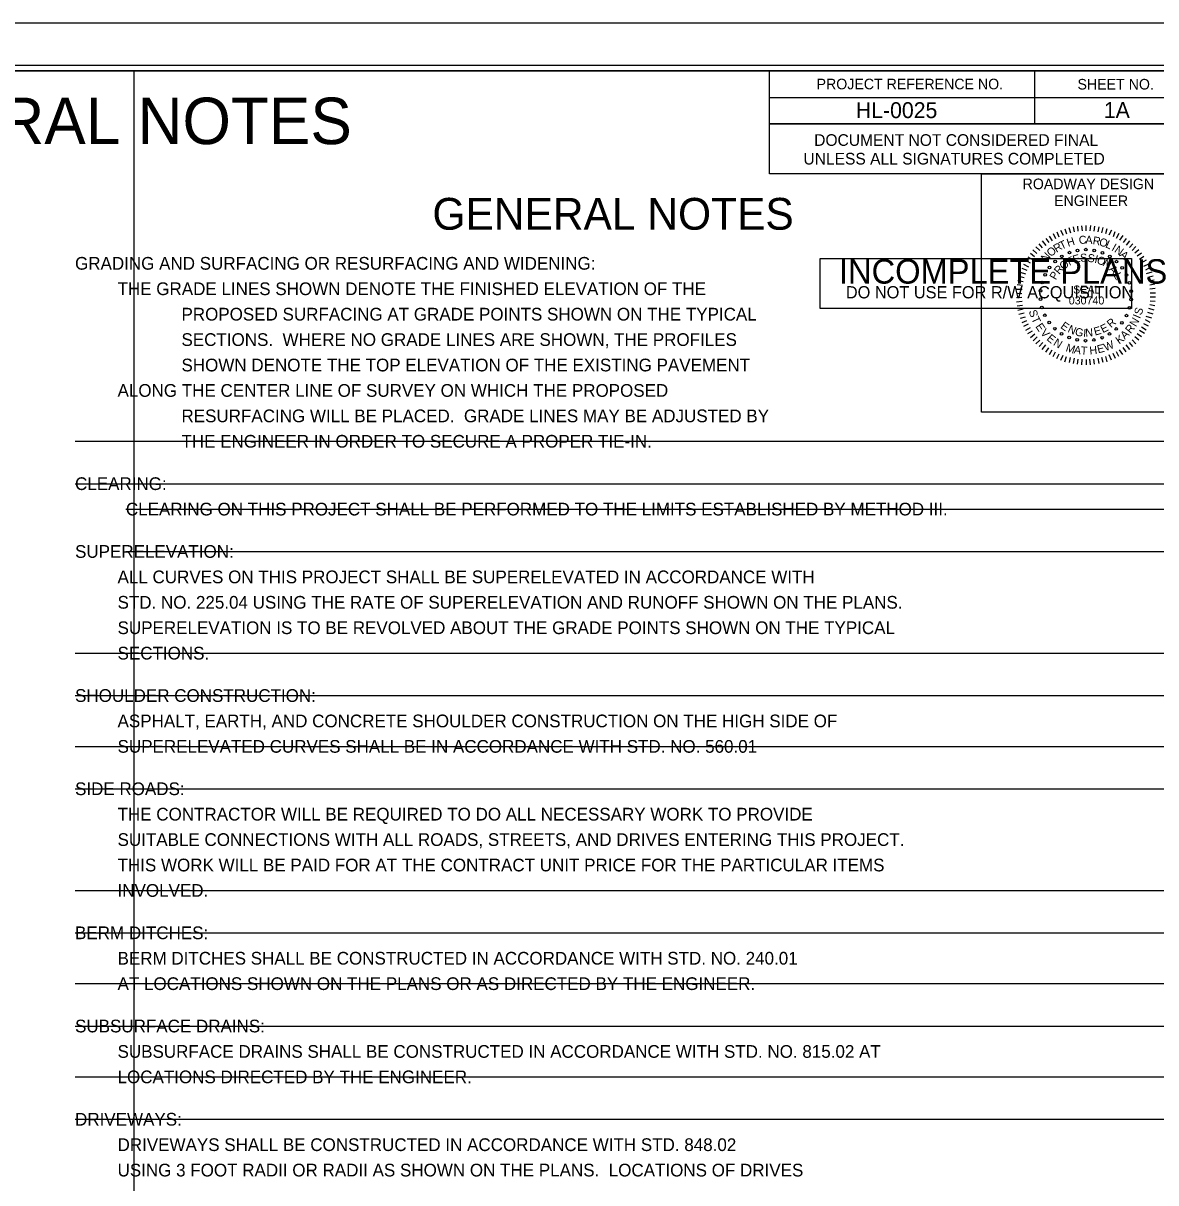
# Model space of a CAD drawing. Extents: x -1492 to 2447, y -56 to 1953.
# Drawn here: x 948 to 1482, y 525 to 1072 of the extents above; entities that cross this region are included whole.
import ezdxf

# ---------------------------------------------------------------- set-up
doc = ezdxf.new("R2010")
doc.units = 0
for name, color, linetype in [('Old_Level_9', 7, 'Continuous'), ('Scratch_Level_3', 7, 'Continuous'), ('Sheet Cutting Line CELL', 7, 'Continuous'), ('Sheet Data Field CELL', 7, 'Continuous'), ('Sheet Data Text CELL', 7, 'Continuous'), ('Sheet Plan CELL', 7, 'Continuous'), ('Sheet Plot Border Inside CELL', 7, 'Continuous'), ('Sheet Plot Border Outside CELL', 7, 'Continuous'), ('Sheet Sticker Exception Certification CELL', 7, 'Continuous'), ('Sheet Sticker Incomplete CELL', 7, 'Continuous'), ('Sheet Summary CELL', 7, 'Continuous')]:
    doc.layers.add(name, color=color, linetype=linetype)

msp = doc.modelspace()

# ---------------------------------------------------------------- linework, layer by layer
at = {"layer": 'Old_Level_9'}
for p, q in [((1437.28, 974.82), (1438.48, 972.42)), ((1439.38, 975.42), (1440.08, 973.02)), ((1441.28, 976.02), (1441.98, 973.52)), ((1443.18, 976.42), (1443.68, 974.02)), ((1445.28, 976.72), (1445.48, 974.32)), ((1447.18, 976.82), (1447.48, 974.42)), ((1449.28, 977.02), (1449.28, 974.42)), ((1451.38, 977.02), (1451.08, 974.42)), ((1453.28, 976.72), (1453.08, 974.32)), ((1455.38, 976.42), (1454.88, 974.02)), ((1457.28, 976.02), (1456.58, 973.62)), ((1459.18, 975.42), (1458.48, 973.02)), ((1461.28, 974.82), (1460.08, 972.42)), ((1428.68, 969.72), (1430.28, 967.62)), ((1430.28, 970.92), (1431.78, 968.92)), ((1431.88, 972.02), (1433.38, 969.82)), ((1433.78, 973.22), (1434.98, 970.82)), ((1435.58, 974.02), (1436.48, 971.72)), ((1462.98, 974.02), (1462.08, 971.72)), ((1464.78, 973.22), (1463.58, 970.82)), ((1466.68, 972.22), (1465.18, 970.02)), ((1468.28, 970.92), (1466.78, 968.92)), ((1469.88, 969.72), (1468.28, 967.72)), ((1423.18, 963.92), (1425.08, 962.32)), ((1424.28, 965.52), (1426.18, 963.82)), ((1425.68, 966.92), (1427.48, 965.22)), ((1427.08, 968.42), (1428.68, 966.52)), ((1471.48, 968.42), (1469.88, 966.62)), ((1472.88, 967.12), (1471.08, 965.22)), ((1474.28, 965.52), (1472.38, 963.92)), ((1475.58, 963.92), (1473.48, 962.52)), ((1419.78, 958.72), (1422.18, 957.52)), ((1420.78, 960.62), (1422.98, 959.32)), ((1421.88, 962.22), (1424.08, 960.92)), ((1476.68, 962.32), (1474.58, 960.92)), ((1477.78, 960.62), (1475.58, 959.32)), ((1478.78, 958.82), (1476.38, 957.72)), ((1417.58, 953.12), (1420.08, 952.42)), ((1418.18, 955.02), (1420.78, 954.22)), ((1418.98, 956.92), (1421.38, 955.92)), ((1479.58, 957.12), (1477.38, 955.92)), ((1480.38, 955.02), (1477.78, 954.22)), ((1480.98, 953.12), (1478.48, 952.42)), ((1416.58, 947.02), (1419.18, 946.92)), ((1416.78, 949.12), (1419.28, 948.82)), ((1417.08, 951.02), (1419.58, 950.52)), ((1481.48, 951.22), (1478.98, 950.72)), ((1481.78, 949.32), (1479.38, 948.82)), ((1481.98, 947.22), (1479.38, 946.92)), ((1416.48, 945.12), (1418.98, 944.92)), ((1416.48, 943.02), (1418.98, 943.22)), ((1482.08, 945.12), (1479.58, 945.12)), ((1482.08, 943.22), (1479.58, 943.22)), ((1416.58, 941.02), (1419.18, 941.32)), ((1416.78, 939.02), (1419.28, 939.42)), ((1417.08, 937.02), (1419.58, 937.62)), ((1481.48, 937.12), (1478.98, 937.82)), ((1481.78, 939.02), (1479.38, 939.52)), ((1481.98, 941.12), (1479.58, 941.32)), ((1417.68, 935.12), (1420.08, 935.72)), ((1418.38, 933.22), (1420.78, 933.92)), ((1419.18, 931.22), (1421.38, 932.22)), ((1419.98, 929.52), (1422.18, 930.62)), ((1478.78, 929.52), (1476.58, 930.62)), ((1479.58, 931.22), (1477.38, 932.42)), ((1480.38, 933.22), (1477.78, 934.12)), ((1480.98, 935.22), (1478.48, 935.92)), ((1420.88, 927.62), (1423.18, 928.82)), ((1421.88, 926.02), (1424.08, 927.32)), ((1423.18, 924.22), (1425.18, 925.82)), ((1475.58, 924.42), (1473.48, 925.82)), ((1476.88, 926.02), (1474.58, 927.42)), ((1477.78, 927.62), (1475.58, 929.02)), ((1424.38, 922.62), (1426.28, 924.42)), ((1425.68, 921.22), (1427.58, 922.92)), ((1427.28, 919.82), (1428.88, 921.72)), ((1428.68, 918.52), (1430.28, 920.62)), ((1469.98, 918.52), (1468.28, 920.62)), ((1471.48, 919.92), (1469.88, 921.72)), ((1472.88, 921.22), (1471.08, 923.12)), ((1474.28, 922.82), (1472.38, 924.42)), ((1430.28, 917.22), (1431.78, 919.32)), ((1432.08, 916.12), (1433.38, 918.32)), ((1433.78, 915.12), (1434.98, 917.42)), ((1435.58, 914.22), (1436.68, 916.42)), ((1437.48, 913.42), (1438.48, 915.82)), ((1439.38, 912.72), (1440.18, 915.12)), ((1441.48, 912.32), (1441.98, 914.72)), ((1443.38, 911.82), (1443.88, 914.32)), ((1455.48, 911.82), (1454.98, 914.32)), ((1457.38, 912.32), (1456.78, 914.72)), ((1459.28, 912.72), (1458.68, 915.12)), ((1461.28, 913.42), (1460.28, 915.92)), ((1463.18, 914.22), (1462.08, 916.62)), ((1464.88, 915.12), (1463.78, 917.42)), ((1466.68, 916.12), (1465.18, 918.32)), ((1468.28, 917.42), (1466.78, 919.42)), ((1445.28, 911.52), (1445.58, 913.92)), ((1447.38, 911.32), (1447.48, 913.92)), ((1449.48, 911.22), (1449.48, 913.72)), ((1451.38, 911.32), (1451.18, 913.92)), ((1453.38, 911.52), (1453.08, 913.92))]:
    msp.add_line(p, q, dxfattribs=at)
for centre in [(1441.51, 964.19), (1445.33, 965.26), (1449.28, 965.61), (1453.23, 965.23), (1457.04, 964.13), (1434.78, 960.06), (1437.95, 962.43), (1460.58, 962.35), (1463.74, 959.94), (1430, 953.77), (1432.1, 957.14), (1466.4, 957), (1468.47, 953.62), (1428.55, 950.08), (1469.89, 949.92), (1427.79, 942.22), (1427.81, 946.19), (1470.59, 942.05), (1470.6, 946.02), (1428.51, 938.32), (1469.84, 938.16), (1429.92, 934.62), (1432, 931.24), (1466.29, 931.1), (1468.39, 934.47), (1434.66, 928.3), (1437.81, 925.9), (1460.44, 925.81), (1463.61, 928.18), (1441.36, 924.11), (1445.17, 923.01), (1449.11, 922.63), (1453.06, 922.98), (1456.88, 924.05)]:
    msp.add_circle(centre, 0.63, dxfattribs=at)
at = {"layer": 'Scratch_Level_3'}
for p, q in [((500, 1050), (1000, 1050)), ((1000, 1050), (1000, -2.5)), ((1000, 1050), (1500, 1050)), ((972.18, 875.15), (1722.72, 875.15)), ((972.18, 855.15), (1722.72, 855.15)), ((996.18, 843.15), (1692.22, 843.15)), ((996.18, 823.15), (1692.22, 823.15)), ((972.18, 775.15), (1722.72, 775.15)), ((972.18, 755.15), (1722.72, 755.15)), ((972.18, 731.15), (1722.72, 731.15)), ((972.18, 711.15), (1722.72, 711.15)), ((972.18, 663.15), (1722.72, 663.15)), ((972.18, 643.15), (1722.72, 643.15)), ((972.18, 619.15), (1722.72, 619.15)), ((972.18, 599.15), (1722.72, 599.15)), ((972.18, 575.15), (1722.72, 575.15)), ((972.18, 555.15), (1722.72, 555.15))]:
    msp.add_line(p, q, dxfattribs=at)
at = {"layer": 'Sheet Cutting Line CELL'}
msp.add_line((1517, 1072.5), (-166.5, 1072.5), dxfattribs=at)
at = {"layer": 'Sheet Plan CELL'}
for p, q in [((1425, 1049.95), (1425, 1024.95)), ((1299.95, 1037.45), (1500, 1037.45)), ((1299.95, 1024.95), (1500, 1024.95)), ((1299.95, 1024.95), (1500, 1024.95))]:
    msp.add_line(p, q, dxfattribs=at)
for points in [[(1500, 1050), (0, 1050), (0, 0), (1500, 0)], [(1299.95, 1050), (1500, 1050), (1500, 1024.95), (1299.95, 1024.95)], [(1399.99, 1001.45), (1499.99, 1001.45), (1499.99, 888.95), (1399.99, 888.95)]]:
    msp.add_lwpolyline(points, close=True, dxfattribs=at)
at = {"layer": 'Sheet Plot Border Inside CELL'}
msp.add_lwpolyline([(-153.5, -2.5), (1512.5, -2.5), (1512.5, 1052.5), (-153.5, 1052.5)], close=True, dxfattribs=at)
at = {"layer": 'Sheet Plot Border Outside CELL'}
msp.add_lwpolyline([(-166.5, -22.5), (1517, -22.5), (1517, 1072.5), (-166.5, 1072.5)], close=True, dxfattribs=at)
at = {"layer": 'Sheet Sticker Exception Certification CELL'}
for p, q in [((1299.95, 1001.45), (1299.95, 1024.95)), ((1299.95, 1024.95), (1499.99, 1024.95)), ((1499.99, 1001.45), (1299.95, 1001.45))]:
    msp.add_line(p, q, dxfattribs=at)
at = {"layer": 'Sheet Sticker Incomplete CELL'}
msp.add_lwpolyline([(1323.77, 937.87), (1323.77, 961.37), (1470.77, 961.37), (1470.77, 937.87)], close=True, dxfattribs=at)

# ---------------------------------------------------------------- texts
at = {"layer": 'Old_Level_9'}
for s, height, rotation, p in [('T', 3.78, 25.4358, (1437.78, 965.52)), ('H', 3.78, 17.7433, (1440.88, 966.92)), ('C', 3.78, 4.9399, (1446.08, 968.22)), ('A', 3.78, 357.9749, (1448.98, 968.42)), ('R', 3.78, 350.0216, (1452.28, 968.22)), ('O', 3.78, 343.0868, (1455.18, 967.72)), ('L', 3.78, 335.7459, (1458.18, 966.82)), ('N', 3.78, 48.0667, (1430.48, 959.52)), ('O', 3.78, 39.9442, (1432.68, 962.02)), ('R', 3.78, 32.1754, (1435.38, 964.12)), ('E', 3.76, 16.5889, (1443.68, 959.02)), ('S', 3.76, 4.468, (1446.68, 959.82)), ('S', 3.76, 353.0415, (1449.88, 959.92)), ('I', 3.78, 330.806, (1461.08, 965.42)), ('N', 3.78, 324.9038, (1462.38, 964.72)), ('A', 3.78, 317.0051, (1464.88, 962.82)), ('R', 3.76, 49.7478, (1436.68, 953.62)), ('O', 3.76, 38.2518, (1438.58, 955.82)), ('F', 3.76, 26.4, (1441.48, 957.92)), ('I', 3.76, 345.4821, (1453.08, 959.52)), ('O', 3.76, 337.8749, (1454.08, 959.32)), ('N', 3.76, 327.393, (1456.78, 958.22)), ('P', 3.76, 60.1236, (1435.08, 951.02)), ('A', 3.76, 313.9438, (1459.78, 956.12)), ('L', 3.76, 301.5323, (1462.18, 953.42)), ('SEAL', 3.759, 360, (1443.24, 944.91)), ('030740', 3.759, 360, (1441.18, 939.75)), ('S', 3.78, 288.212, (1422.23, 936.54)), ('S', 3.78, 72.2579, (1475.46, 934.43)), ('T', 3.78, 295.6244, (1423.42, 933.02)), ('E', 3.78, 303.8225, (1425.29, 929.34)), ('E', 3.76, 324.8692, (1436.98, 928.82)), ('E', 3.76, 27.1568, (1457.28, 926.12)), ('R', 3.76, 40.3493, (1461.08, 928.52)), ('N', 3.78, 59.3726, (1472.83, 928.94)), ('I', 3.78, 66.0464, (1474.76, 932.74)), ('V', 3.78, 311.9298, (1427.55, 926.16)), ('E', 3.78, 320.2312, (1430.44, 923.19)), ('N', 3.76, 336.0584, (1440.38, 926.82)), ('G', 3.76, 347.4812, (1443.88, 925.22)), ('I', 3.76, 355.6246, (1447.88, 924.52)), ('N', 3.76, 3.1278, (1449.08, 924.52)), ('E', 3.76, 15.8057, (1453.58, 925.02)), ('K', 3.78, 36.141, (1464.98, 920.76)), ('A', 3.78, 43.5217, (1467.61, 923.03)), ('R', 3.78, 51.1503, (1470.37, 925.7)), ('N', 3.78, 328.329, (1433.57, 920.76)), ('M', 3.78, 342.337, (1439.48, 917.76)), ('A', 3.78, 350.1822, (1443.37, 916.73)), ('T', 3.78, 357.3866, (1446.78, 916.17)), ('H', 3.78, 6.0112, (1451.13, 916.06)), ('E', 3.78, 14.1648, (1455.07, 916.64)), ('W', 3.78, 22.0058, (1458.53, 917.6))]:
    msp.add_text(s, height=height, rotation=rotation, dxfattribs=at).set_placement(p)
at = {"layer": 'Sheet Data Field CELL'}
for s, height, p in [('HL-0025', 7.5, (1340.68, 1027.7)), ('1A', 7.5, (1457.72, 1027.75)), ('GENERAL NOTES', 15, (1140.84, 975.02))]:
    msp.add_text(s, height=height, dxfattribs=at).set_placement(p)
at = {"layer": 'Sheet Data Text CELL'}
for s, p in [('GRADING AND SURFACING OR RESURFACING AND WIDENING:  ', (972.18, 956.15)), ('         THE GRADE LINES SHOWN DENOTE THE FINISHED ELEVATION OF THE', (972.18, 944.15)), (' PROPOSED SURFACING AT GRADE POINTS SHOWN ON THE TYPICAL', (1020.18, 932.15)), (' SECTIONS.  WHERE NO GRADE LINES ARE SHOWN, THE PROFILES', (1020.18, 920.15)), (' SHOWN DENOTE THE TOP ELEVATION OF THE EXISTING PAVEMENT ', (1020.18, 908.15)), ('         ALONG THE CENTER LINE OF SURVEY ON WHICH THE PROPOSED', (972.18, 896.15)), (' RESURFACING WILL BE PLACED.  GRADE LINES MAY BE ADJUSTED BY', (1020.18, 884.15)), (' THE ENGINEER IN ORDER TO SECURE A PROPER TIE-IN. ', (1020.18, 872.15)), ('CLEARING:', (972.18, 852.15)), ('CLEARING ON THIS PROJECT SHALL BE PERFORMED TO THE LIMITS ESTABLISHED BY METHOD III.', (996.18, 840.15)), ('SUPERELEVATION:  ', (972.18, 820.15)), ('         ALL CURVES ON THIS PROJECT SHALL BE SUPERELEVATED IN ACCORDANCE WITH', (972.18, 808.15)), ('         STD. NO. 225.04 USING THE RATE OF SUPERELEVATION AND RUNOFF SHOWN ON THE PLANS.', (972.18, 796.15)), ('         SUPERELEVATION IS TO BE REVOLVED ABOUT THE GRADE POINTS SHOWN ON THE TYPICAL ', (972.18, 784.15)), ('         SECTIONS.', (972.18, 772.15)), ('SHOULDER CONSTRUCTION:  ', (972.18, 752.15)), ('         ASPHALT, EARTH, AND CONCRETE SHOULDER CONSTRUCTION ON THE HIGH SIDE OF', (972.18, 740.15)), ('         SUPERELEVATED CURVES SHALL BE IN ACCORDANCE WITH STD. NO. 560.01', (972.18, 728.15)), ('SIDE ROADS:  ', (972.18, 708.15)), ('         THE CONTRACTOR WILL BE REQUIRED TO DO ALL NECESSARY WORK TO PROVIDE ', (972.18, 696.15)), ('         SUITABLE CONNECTIONS WITH ALL ROADS, STREETS, AND DRIVES ENTERING THIS PROJECT.  ', (972.18, 684.15)), ('         THIS WORK WILL BE PAID FOR AT THE CONTRACT UNIT PRICE FOR THE PARTICULAR ITEMS ', (972.18, 672.15)), ('         INVOLVED.', (972.18, 660.15)), ('BERM DITCHES:  ', (972.18, 640.15)), ('         BERM DITCHES SHALL BE CONSTRUCTED IN ACCORDANCE WITH STD. NO. 240.01 ', (972.18, 628.15)), ('         AT LOCATIONS SHOWN ON THE PLANS OR AS DIRECTED BY THE ENGINEER.', (972.18, 616.15)), ('SUBSURFACE DRAINS:', (972.18, 596.15)), ('         SUBSURFACE DRAINS SHALL BE CONSTRUCTED IN ACCORDANCE WITH STD. NO. 815.02 AT ', (972.18, 584.15)), ('         LOCATIONS DIRECTED BY THE ENGINEER.', (972.18, 572.15)), ('DRIVEWAYS:  ', (972.18, 552.15)), ('         DRIVEWAYS SHALL BE CONSTRUCTED IN ACCORDANCE WITH STD. 848.02', (972.18, 540.15)), ('         USING 3 FOOT RADII OR RADII AS SHOWN ON THE PLANS.  LOCATIONS OF DRIVES', (972.18, 528.15))]:
    msp.add_text(s, height=6, dxfattribs=at).set_placement(p)
at = {"layer": 'Sheet Plan CELL'}
for s, height, p in [('PROJECT REFERENCE NO.', 5.0001, (1322.15, 1041.3)), ('SHEET NO.', 5, (1445.3, 1041.2)), ('ROADWAY DESIGN', 5.0001, (1419.39, 994.15)), ('ENGINEER', 5, (1434.24, 986.2))]:
    msp.add_text(s, height=height, dxfattribs=at).set_placement(p)
at = {"layer": 'Sheet Sticker Exception Certification CELL'}
for s, p in [('DOCUMENT NOT CONSIDERED FINAL', (1321.02, 1014.6)), ('UNLESS ALL SIGNATURES COMPLETED', (1315.95, 1005.8))]:
    msp.add_text(s, height=5.5, dxfattribs=at).set_placement(p)
at = {"layer": 'Sheet Sticker Incomplete CELL'}
for s, height, p in [('INCOMPLETE PLANS', 11.52, (1332.72, 949.57)), ('DO NOT USE FOR R/W ACQUISITION', 5.76, (1335.97, 942.62))]:
    msp.add_text(s, height=height, dxfattribs=at).set_placement(p)
at = {"layer": 'Sheet Summary CELL'}
msp.add_text('INDEX OF SHEETS,  LIST OF STANDARD DRAWINGS,  & GENERAL NOTES', height=21.9501, dxfattribs=at).set_placement((62.29, 1015.41))

doc.saveas('drawing.dxf')
